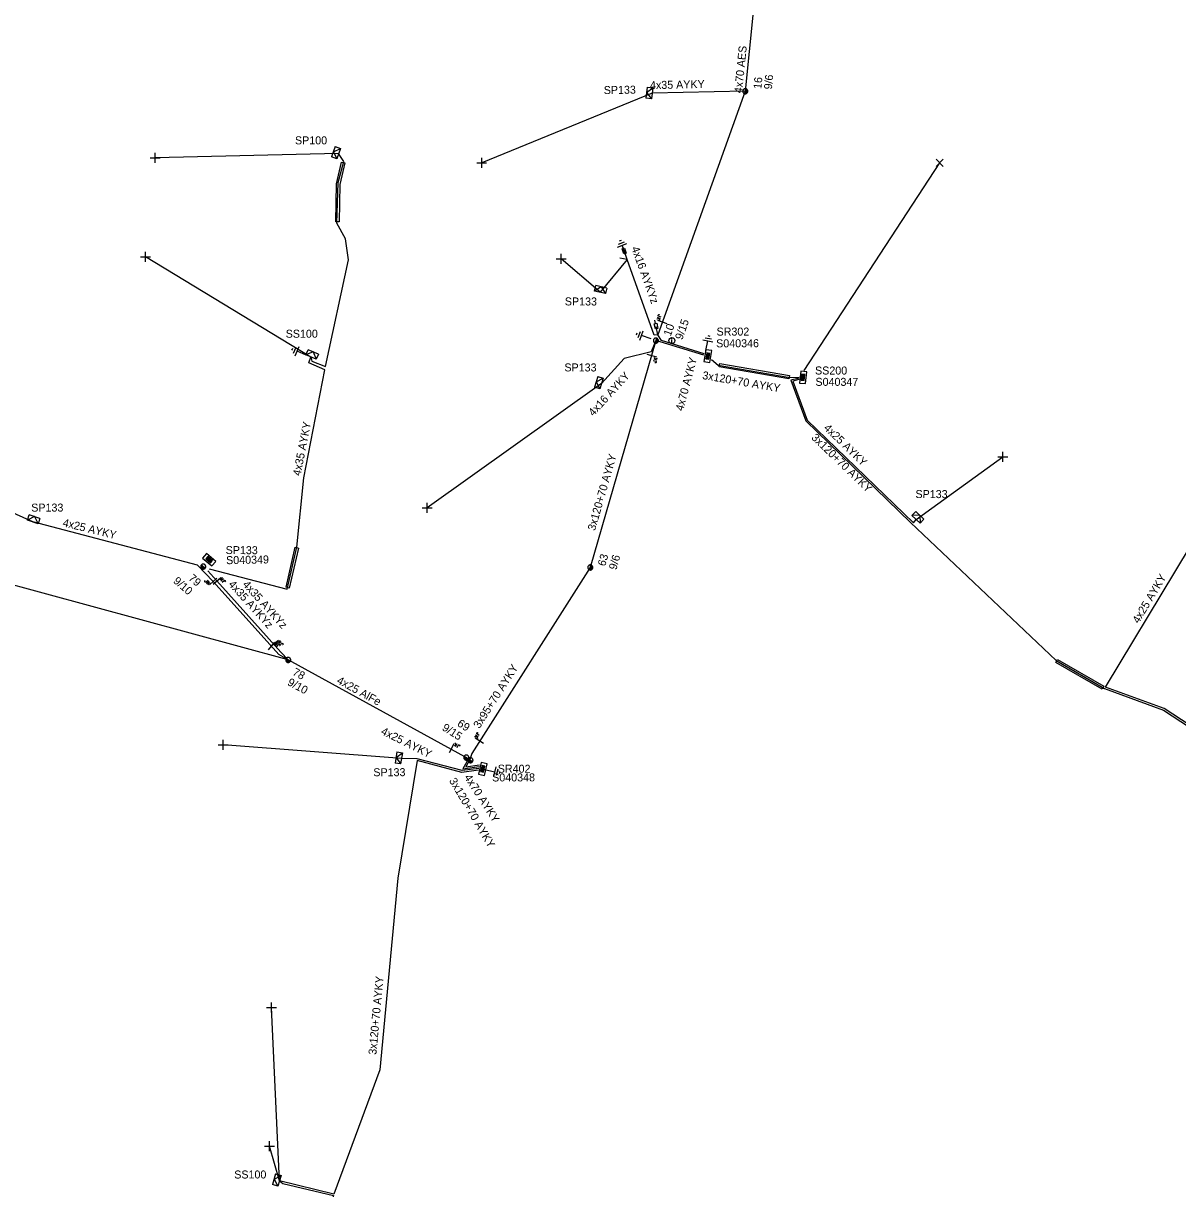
# Model space of a CAD drawing. Extents: x -748492 to -735633, y -1146251 to -1139940.
# Drawn here: x -741045.2 to -740901, y -1144241 to -1144095.3 of the extents above; entities that cross this region are included whole.
import ezdxf

# ---------------------------------------------------------------- set-up
doc = ezdxf.new("R2010")
doc.units = 0
for name, color, linetype in [('Vrstva 1', 7, 'Continuous'), ('Vrstva 10', 7, 'Continuous'), ('Vrstva 12', 7, 'Continuous'), ('Vrstva 13', 7, 'Continuous'), ('Vrstva 14', 7, 'Continuous'), ('Vrstva 15', 7, 'Continuous'), ('Vrstva 16', 7, 'Continuous'), ('Vrstva 18', 7, 'Continuous'), ('Vrstva 2', 7, 'Continuous'), ('Vrstva 20', 7, 'Continuous'), ('Vrstva 28', 7, 'Continuous'), ('Vrstva 29', 7, 'Continuous'), ('Vrstva 30', 7, 'Continuous'), ('Vrstva 31', 7, 'Continuous'), ('Vrstva 33', 7, 'Continuous'), ('Vrstva 34', 7, 'Continuous'), ('Vrstva 36', 7, 'Continuous'), ('Vrstva 5', 7, 'Continuous'), ('Vrstva 50', 7, 'Continuous'), ('Vrstva 51', 7, 'Continuous'), ('Vrstva 52', 7, 'Continuous'), ('Vrstva 53', 7, 'Continuous'), ('Vrstva 54', 7, 'Continuous'), ('Vrstva 55', 7, 'Continuous'), ('Vrstva 59', 7, 'Continuous'), ('Vrstva 6', 7, 'Continuous'), ('Vrstva 8', 7, 'Continuous'), ('Vrstva 9', 7, 'Continuous')]:
    doc.layers.add(name, color=color, linetype=linetype)

# ---------------------------------------------------------------- blocks, each defined once
blk = doc.blocks.new('NN440')
at = {"layer": 'Vrstva 2'}
for points in [[(0.63, 0), (0.63, 0.06), (0.62, 0.13), (0.6, 0.19), (0.58, 0.25), (0.55, 0.31), (0.51, 0.37), (0.47, 0.42), (0.42, 0.46), (0.37, 0.51), (0.32, 0.54), (0.26, 0.57), (0.2, 0.59), (0.13, 0.61), (0.07, 0.62), (0, 0.63), (-0.06, 0.62), (-0.13, 0.61), (-0.19, 0.59), (-0.26, 0.57), (-0.31, 0.54), (-0.37, 0.51), (-0.42, 0.46), (-0.47, 0.42), (-0.51, 0.37), (-0.54, 0.31), (-0.57, 0.25), (-0.6, 0.19), (-0.62, 0.13), (-0.63, 0.06), (-0.63, 0), (-0.63, -0.07), (-0.62, -0.14), (-0.6, -0.2), (-0.57, -0.26), (-0.54, -0.32), (-0.51, -0.37), (-0.47, -0.43), (-0.42, -0.47), (-0.37, -0.51), (-0.31, -0.55), (-0.26, -0.58), (-0.19, -0.6), (-0.13, -0.62), (-0.06, -0.63), (0, -0.63), (0.07, -0.63), (0.13, -0.62), (0.2, -0.6), (0.26, -0.58), (0.32, -0.55), (0.37, -0.51), (0.42, -0.47), (0.47, -0.43), (0.51, -0.37), (0.55, -0.32), (0.58, -0.26), (0.6, -0.2), (0.62, -0.14), (0.63, -0.07), (0.63, 0)], [(-0.63, 0), (0.63, 0)], [(-0.6, -0.18), (0.57, -0.18)], [(-0.51, -0.32), (0.5, -0.32)], [(-0.37, -0.47), (0.35, -0.47)]]:
    blk.add_lwpolyline(points, dxfattribs=at)
blk = doc.blocks.new('NN450')
at = {"layer": 'Vrstva 2'}
for points in [[(0, 0), (0, 0.07), (-0.01, 0.13), (-0.03, 0.19), (-0.05, 0.25), (-0.08, 0.31), (-0.12, 0.37), (-0.16, 0.42), (-0.21, 0.46), (-0.26, 0.51), (-0.31, 0.54), (-0.37, 0.57), (-0.43, 0.59), (-0.5, 0.61), (-0.56, 0.62), (-0.63, 0.62), (-0.69, 0.62), (-0.75, 0.61), (-0.82, 0.59), (-0.88, 0.57), (-0.94, 0.54), (-0.99, 0.51), (-1.04, 0.46), (-1.09, 0.42), (-1.13, 0.37), (-1.17, 0.31), (-1.2, 0.25), (-1.22, 0.19), (-1.24, 0.13), (-1.25, 0.07), (-1.25, 0), (-1.25, -0.07), (-1.24, -0.13), (-1.22, -0.19), (-1.2, -0.25), (-1.17, -0.31), (-1.13, -0.37), (-1.09, -0.42), (-1.04, -0.46), (-0.99, -0.51), (-0.94, -0.54), (-0.88, -0.57), (-0.82, -0.59), (-0.75, -0.61), (-0.69, -0.62), (-0.62, -0.63), (-0.56, -0.62), (-0.5, -0.61), (-0.43, -0.59), (-0.37, -0.57), (-0.31, -0.54), (-0.26, -0.51), (-0.21, -0.46), (-0.16, -0.42), (-0.12, -0.37), (-0.08, -0.31), (-0.05, -0.25), (-0.03, -0.19), (-0.01, -0.13), (0, -0.07), (0, 0)], [(1.25, 0), (1.25, 0.07), (1.24, 0.13), (1.22, 0.19), (1.2, 0.25), (1.17, 0.31), (1.13, 0.37), (1.09, 0.42), (1.04, 0.46), (0.99, 0.51), (0.94, 0.54), (0.88, 0.57), (0.82, 0.59), (0.75, 0.61), (0.69, 0.62), (0.62, 0.62), (0.56, 0.62), (0.5, 0.61), (0.43, 0.59), (0.37, 0.57), (0.31, 0.54), (0.26, 0.51), (0.21, 0.46), (0.16, 0.42), (0.12, 0.37), (0.08, 0.31), (0.05, 0.25), (0.03, 0.19), (0.01, 0.13), (0, 0.07), (0, 0), (0, -0.07), (0.01, -0.13), (0.03, -0.19), (0.05, -0.25), (0.08, -0.31), (0.12, -0.37), (0.16, -0.42), (0.21, -0.46), (0.26, -0.51), (0.31, -0.54), (0.37, -0.57), (0.43, -0.59), (0.5, -0.61), (0.56, -0.62), (0.63, -0.63), (0.69, -0.62), (0.75, -0.61), (0.82, -0.59), (0.88, -0.57), (0.94, -0.54), (0.99, -0.51), (1.04, -0.46), (1.09, -0.42), (1.13, -0.37), (1.17, -0.31), (1.2, -0.25), (1.22, -0.19), (1.24, -0.13), (1.25, -0.07), (1.25, 0)], [(-1.25, 0), (1.25, 0)], [(-1.23, -0.16), (-0.02, -0.16)], [(-1.16, -0.32), (-0.09, -0.32)], [(-1.03, -0.47), (-0.22, -0.47)], [(0.02, -0.16), (1.23, -0.16)], [(0.09, -0.32), (1.16, -0.32)], [(0.22, -0.47), (1.03, -0.47)]]:
    blk.add_lwpolyline(points, dxfattribs=at)
blk = doc.blocks.new('NN840')
at = {"layer": 'Vrstva 15'}
for points in [[(0, 0.62), (0, -0.63)], [(-0.75, -0.71), (-0.75, -0.66)], [(-0.73, -0.76), (-0.75, -0.71)], [(-0.66, -0.8), (-0.73, -0.76)], [(-0.63, -0.8), (-0.66, -0.8)], [(-0.56, -0.76), (-0.63, -0.8)], [(-0.54, -0.71), (-0.56, -0.76)], [(-0.54, -0.38), (-0.54, -0.71)], [(-0.33, -0.38), (-0.33, -0.8)], [(-0.33, -0.64), (-0.13, -0.38)], [(-0.26, -0.56), (-0.09, -0.8)]]:
    blk.add_lwpolyline(points, dxfattribs=at)
blk = doc.blocks.new('NN770')
at = {"layer": 'Vrstva 10'}
for p, q in [((0, 0.19), (0, 0.26)), ((0, -0.28), (0, 0.11))]:
    blk.add_line(p, q, dxfattribs=at)
blk.add_circle((0, -0.01), 0.375, dxfattribs=at)
blk = doc.blocks.new('NN800')
at = {"layer": 'Vrstva 1'}
for points in [[(-0.44, 0.44), (0.44, -0.44)], [(-0.44, -0.44), (0.44, 0.44)]]:
    blk.add_lwpolyline(points, dxfattribs=at)
blk = doc.blocks.new('NN820')
at = {"layer": 'Vrstva 13'}
for points in [[(0, 0), (0, -1.05)], [(-0.16, -0.81), (0.16, -0.81)], [(-0.16, -1.47), (-0.16, -0.81)], [(0, -1.05), (-0.06, -0.93)], [(0, -1.05), (0.06, -0.93)], [(0.16, -0.81), (0.16, -1.47)], [(0.16, -1.47), (-0.16, -1.47)], [(0, -1.47), (0, -1.87)]]:
    blk.add_lwpolyline(points, dxfattribs=at)
blk = doc.blocks.new('NN620')
at = {"layer": 'Vrstva 8'}
for points in [[(0.75, 0), (-0.75, 0)], [(-0.75, 0), (-0.75, -0.75)], [(0.75, -0.75), (0.75, 0)], [(-0.75, -0.75), (0.75, -0.75)], [(0.37, -0.18), (-0.38, -0.18)], [(-0.38, -0.18), (-0.38, -0.56)], [(-0.38, -0.56), (0.37, -0.56)], [(0.32, -0.23), (-0.33, -0.23)], [(-0.33, -0.23), (-0.33, -0.51)], [(-0.33, -0.51), (0.32, -0.51)], [(0.27, -0.27), (-0.28, -0.27)], [(-0.28, -0.27), (-0.28, -0.46)], [(-0.28, -0.46), (0.27, -0.46)], [(0.23, -0.32), (-0.23, -0.32)], [(-0.23, -0.32), (-0.23, -0.42)], [(-0.23, -0.42), (0.23, -0.42)], [(-0.19, -0.37), (0.19, -0.37)], [(0.23, -0.42), (0.23, -0.32)], [(0.27, -0.46), (0.27, -0.27)], [(0.32, -0.51), (0.32, -0.23)], [(0.37, -0.56), (0.37, -0.18)]]:
    blk.add_lwpolyline(points, dxfattribs=at)
blk = doc.blocks.new('NN630')
at = {"layer": 'Vrstva 9'}
for points in [[(0, -0.7), (-0.7, 0)], [(-0.7, -0.7), (-0.7, 0), (0.7, 0), (0.7, -0.7)], [(-0.7, -0.7), (0.7, -0.7)], [(0, -0.7), (0.7, 0)]]:
    blk.add_lwpolyline(points, dxfattribs=at)
blk = doc.blocks.new('NN810')
at = {"layer": 'Vrstva 14'}
for points in [[(0, -0.64), (0, -1.89)], [(0.63, -1.89), (-0.62, -1.89)], [(0.39, -2.2), (-0.4, -2.2)], [(0, -2.52), (-0.12, -2.52)], [(0.14, -2.52), (0, -2.52)]]:
    blk.add_lwpolyline(points, dxfattribs=at)
blk = doc.blocks.new('NN510')
at = {"layer": 'Vrstva 2'}
blk.add_lwpolyline([(0, 0), (0, 0.94)], dxfattribs=at)

msp = doc.modelspace()

# ---------------------------------------------------------------- linework, layer by layer
at = {"layer": 'Vrstva 1'}
for points in [[(-741012.12, -1144174.87), (-741048.89, -1144164.86), (-741086.24, -1144154.83), (-741116.25, -1144144.94)], [(-740989.6, -1144187.24), (-741012.12, -1144174.87)]]:
    msp.add_lwpolyline(points, dxfattribs=at)
at = {"layer": 'Vrstva 20'}
for points in [[(-741005.44, -1144112.67), (-741005.03, -1144112.77), (-741005.67, -1144115.44), (-741005.74, -1144120.13), (-741006.17, -1144120.12), (-741006.1, -1144115.39)], [(-740958.18, -1144137.82), (-740949.47, -1144139.32), (-740949.54, -1144139.74), (-740958.25, -1144138.25)], [(-741012.39, -1144165.8), (-741011.24, -1144160.8), (-741010.84, -1144160.89), (-741012, -1144165.89)], [(-740916.2, -1144175.18), (-740915.98, -1144174.81), (-740910.2, -1144178.17), (-740910.41, -1144178.54)]]:
    msp.add_lwpolyline(points, close=True, dxfattribs=at)
at = {"layer": 'Vrstva 5'}
for points in [[(-741022.01, -1144163.47), (-741012.24, -1144166.05), (-741011.03, -1144160.8), (-741010.17, -1144152.11), (-741007.52, -1144138.63), (-741009.56, -1144137.76), (-741009.27, -1144137.02), (-741009.17, -1144137.55), (-741007.44, -1144138.2), (-741004.59, -1144124.87), (-741004.95, -1144122.26), (-741006.05, -1144120.28), (-741005.89, -1144115.23), (-741005.18, -1144112.58), (-741005.82, -1144111.59)], [(-740960.14, -1144136.6), (-740965.46, -1144134.97), (-740965.92, -1144134.26)], [(-740960.17, -1144136.8), (-740966.17, -1144134.96)], [(-740959.24, -1144137.32), (-740958.39, -1144138.02), (-740949.44, -1144139.56), (-740948.28, -1144139.52)], [(-740948.28, -1144139.66), (-740949.32, -1144139.9), (-740947.42, -1144145.01), (-740934.34, -1144157.68), (-740916.13, -1144174.95), (-740910.1, -1144178.46), (-740902.73, -1144181.13), (-740885.4, -1144192.49), (-740885.11, -1144192.16)], [(-740989.6, -1144187.24), (-740990.28, -1144188.5), (-740988.24, -1144188.21)], [(-740989.18, -1144186.57), (-740989.42, -1144187.33), (-740989.92, -1144188.25), (-740988.2, -1144188)], [(-740988.35, -1144188.63), (-740990.41, -1144188.92), (-740996.02, -1144187.44), (-740998.41, -1144202.15), (-741000.67, -1144226.1), (-741006.41, -1144241.62), (-741013.22, -1144239.98), (-741012.79, -1144240.29), (-741006.47, -1144241.81), (-741012.77, -1144265.77), (-741010.65, -1144272.99), (-741011.74, -1144282.71), (-741012.93, -1144282.43)]]:
    msp.add_lwpolyline(points, dxfattribs=at)
at = {"layer": 'Vrstva 50'}
msp.add_lwpolyline([(-740946.1, -1144042.17), (-740951.92, -1144073.19), (-740955, -1144103.8), (-740965.92, -1144134.26)], dxfattribs=at)
at = {"layer": 'Vrstva 52'}
for points in [[(-740955, -1144103.8), (-740966.64, -1144104.06)], [(-740885.27, -1144192.03), (-740885.46, -1144192.21), (-740902.64, -1144180.95), (-740909.99, -1144178.29), (-740883.61, -1144134.55), (-740882.09, -1144133.72)], [(-740966.17, -1144134.96), (-740974.37, -1144163.32), (-740989.18, -1144186.57)], [(-740966.17, -1144134.96), (-740966.77, -1144136.35), (-740970.14, -1144137.21), (-740972.97, -1144140.32)], [(-740948.3, -1144139.82), (-740949.06, -1144140.02), (-740947.25, -1144144.9), (-740933.99, -1144157.73), (-740933.66, -1144157.31)], [(-741023.46, -1144163.01), (-741044.03, -1144157.63)], [(-741012.12, -1144174.87), (-741013.28, -1144174.21), (-741021.49, -1144165.08), (-741023.46, -1144163.01)], [(-741022.17, -1144163.73), (-741021.02, -1144164.99), (-741013.02, -1144173.89), (-741012.12, -1144174.87)], [(-740988.29, -1144188.42), (-740990.39, -1144188.71), (-740995.99, -1144187.24), (-740997.95, -1144187.18)]]:
    msp.add_lwpolyline(points, dxfattribs=at)
at = {"layer": 'Vrstva 54'}
msp.add_lwpolyline([(-740965.92, -1144134.26), (-740966.4, -1144134.3), (-740969.74, -1144124.84), (-740973.15, -1144128.93)], dxfattribs=at)
at = {"layer": 'Vrstva 59'}
for points in [[(-740966.64, -1144104.06), (-740987.94, -1144112.75)], [(-741005.82, -1144111.6), (-741028.75, -1144112.13)], [(-740947.63, -1144138.7), (-740930.69, -1144112.75)], [(-741009.27, -1144137.02), (-741029.94, -1144124.5)], [(-740973.15, -1144128.93), (-740978, -1144124.75)], [(-740972.97, -1144140.32), (-740994.75, -1144155.88)], [(-741044.03, -1144157.63), (-741076.63, -1144143)], [(-740933.66, -1144157.31), (-740922.81, -1144149.5)], [(-740997.95, -1144187.18), (-741020.25, -1144185.5)], [(-741013.22, -1144239.98), (-741014.19, -1144218.3)], [(-741013.22, -1144239.98), (-741014.45, -1144235.62)]]:
    msp.add_lwpolyline(points, dxfattribs=at)

# ---------------------------------------------------------------- block references
at = {"layer": 'Vrstva 13'}
for name, p, xscale, yscale, rotation in [('NN440', (-740955, -1144103.8), 0.49999999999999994, 0.5000000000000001, 84.2955472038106), ('NN440', (-740966.17, -1144134.96), 0.5, 0.5, 70.52858330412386), ('NN440', (-741022.73, -1144163.2), 0.5, 0.5, -40.86051949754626), ('NN440', (-740974.37, -1144163.32), 0.5, 0.5, 73.87332228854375), ('NN440', (-741012.12, -1144174.87), 0.5, 0.5, -28.28923612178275), ('NN450', (-740989.6, -1144187.24), 0.5, 0.5000000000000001, -32.633441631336)]:
    msp.add_blockref(name, p, dxfattribs=dict(at, xscale=xscale, yscale=yscale, rotation=rotation))
at = {"layer": 'Vrstva 13', "rotation": 78.00008328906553}
msp.add_blockref('NN510', (-740969.74, -1144124.84), dxfattribs=at)
at = {"layer": 'Vrstva 15'}
for p, rotation in [((-740969.74, -1144124.84), -160.2392472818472), ((-740966.17, -1144134.96), -109.4714166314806), ((-740960.05, -1144136.84), 168.6360666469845), ((-741009.27, -1144137.02), -112.95754439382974), ((-740988.16, -1144188.4), 76.60303609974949)]:
    msp.add_blockref('NN810', p, dxfattribs=dict(at, rotation=rotation))
at = {"layer": 'Vrstva 16'}
for p, rotation in [((-740969.74, -1144124.84), -160.2392472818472), ((-740965.92, -1144134.26), -168.5325388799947)]:
    msp.add_blockref('NN820', p, dxfattribs=dict(at, rotation=rotation))
at = {"layer": 'Vrstva 18'}
for p, rotation in [((-740965.35, -1144132.67), -110.33704722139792), ((-740966.71, -1144136.84), 73.8170500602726), ((-741021.49, -1144165.08), -48.44668063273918), ((-741021.02, -1144164.99), 131.07454443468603), ((-741014.19, -1144173.13), 138.61206670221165), ((-741013.82, -1144172.79), 126.60870547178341), ((-740988.23, -1144184.99), -123.71592498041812), ((-740991.67, -1144185.88), 151.71076391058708)]:
    msp.add_blockref('NN840', p, dxfattribs=dict(at, rotation=rotation))
at = {"layer": 'Vrstva 28'}
for p, rotation in [((-740960.05, -1144136.84), 80.7175583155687), ((-740948.14, -1144139.52), 84.01704442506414), ((-741022.24, -1144162.63), 139.13899995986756), ((-740988.16, -1144188.4), 76.68470000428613)]:
    msp.add_blockref('NN620', p, dxfattribs=dict(at, rotation=rotation))
at = {"layer": 'Vrstva 31'}
for p, rotation in [((-740966.64, -1144104.06), -96.95990000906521), ((-741005.82, -1144111.6), -109.9655860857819), ((-740973.15, -1144128.93), 167.5300471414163), ((-741009.27, -1144137.02), 157.04245551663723), ((-740972.97, -1144140.32), -107.82400830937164), ((-740933.66, -1144157.31), 136.7943583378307), ((-741044.03, -1144157.63), 161.63737237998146), ((-740997.95, -1144187.18), -99.3960388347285), ((-741013.22, -1144239.98), -106.94598609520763)]:
    msp.add_blockref('NN630', p, dxfattribs=dict(at, rotation=rotation))
at = {"layer": 'Vrstva 34'}
for p, rotation in [((-741028.75, -1144112.13), 45), ((-740987.94, -1144112.75), 44.99999995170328), ((-741029.94, -1144124.5), 44.99999995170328), ((-740978, -1144124.75), 45), ((-740922.81, -1144149.5), 45), ((-740994.75, -1144155.88), 45), ((-741020.25, -1144185.5), 45), ((-741014.19, -1144218.3), 45), ((-741014.45, -1144235.62), 45.000000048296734)]:
    msp.add_blockref('NN800', p, dxfattribs=dict(at, rotation=rotation))
msp.add_blockref('NN800', (-740930.69, -1144112.75), dxfattribs=at)
at = {"layer": 'Vrstva 36'}
msp.add_blockref('NN770', (-740964.17, -1144134.96), dxfattribs=at)

# ---------------------------------------------------------------- texts
at = {"layer": 'Vrstva 12'}
for s, rotation, p in [('9/6', 84.296, (-740951.68, -1144103.62)), ('9/15', 70.529, (-740962.88, -1144134.95)), ('9/6', 73.873, (-740971.12, -1144163.69)), ('9/10', 319.139, (-741026.57, -1144165.13)), ('9/10', 331.711, (-741012.3, -1144177.96)), ('9/15', 327.367, (-740992.98, -1144183.57))]:
    msp.add_text(s, height=1, rotation=rotation, dxfattribs=at).set_placement(p)
at = {"layer": 'Vrstva 14'}
for s, rotation, p in [('16', 84.296, (-740953, -1144103.56)), ('10', 70.529, (-740964.32, -1144134.49)), ('63', 73.873, (-740972.51, -1144163.23)), ('79', 319.139, (-741024.67, -1144164.79)), ('78', 331.711, (-741011.67, -1144176.69)), ('69', 327.367, (-740991.08, -1144183.05))]:
    msp.add_text(s, height=1, rotation=rotation, dxfattribs=at).set_placement(p)
at = {"layer": 'Vrstva 2'}
msp.add_text('4x25 AlFe', height=1, rotation=331.22, dxfattribs=at).set_placement((-741006.14, -1144177.73))
at = {"layer": 'Vrstva 29'}
for s, rotation, p in [('S040346', 0.183, (-740958.64, -1144135.81)), ('S040347', 359.952, (-740946.23, -1144140.62)), ('S040349', 1.106, (-741019.87, -1144162.91)), ('S040348', 0.14, (-740986.63, -1144190.06))]:
    msp.add_text(s, height=1, rotation=rotation, dxfattribs=at).set_placement(p)
at = {"layer": 'Vrstva 30'}
for s, rotation, p in [('SR302', 359.99, (-740958.59, -1144134.34)), ('SS200', 359.839, (-740946.28, -1144139.2)), ('SP133', 359.622, (-741019.94, -1144161.64)), ('SR402', 359.832, (-740985.93, -1144188.96))]:
    msp.add_text(s, height=1, rotation=rotation, dxfattribs=at).set_placement(p)
at = {"layer": 'Vrstva 33'}
for s, rotation, p in [('SP133', 0.776, (-740972.68, -1144104.16)), ('SP100', 359.93, (-741011.27, -1144110.44)), ('SP133', 359.88, (-740977.55, -1144130.57)), ('SS100', 0.08, (-741012.43, -1144134.61)), ('SP133', 359.983, (-740977.6, -1144138.82)), ('SP133', 359.86, (-740933.73, -1144154.64)), ('SP133', 0.126, (-741044.23, -1144156.34)), ('SP133', 0.148, (-741001.48, -1144189.41)), ('SS100', 0.125, (-741018.86, -1144239.68))]:
    msp.add_text(s, height=1, rotation=rotation, dxfattribs=at).set_placement(p)
at = {"layer": 'Vrstva 51'}
msp.add_text('4x70 AES', height=1, rotation=84.254, dxfattribs=at).set_placement((-740955.4, -1144104.09))
at = {"layer": 'Vrstva 53'}
for s, rotation, p in [('4x35 AYKYz', 312.008, (-741019.66, -1144165.47)), ('4x35 AYKYz', 312.005, (-741017.89, -1144165.5)), ('3x95+70 AYKY', 57.514, (-740988.22, -1144183.52))]:
    msp.add_text(s, height=1, rotation=rotation, dxfattribs=at).set_placement(p)
at = {"layer": 'Vrstva 54'}
for s, rotation, p in [('4x35 AYKY', 1.28, (-740966.9, -1144103.55)), ('4x16 AYKY', 47.521, (-740973.98, -1144144.49)), ('4x25 AYKY', 315.919, (-740945.27, -1144145.98)), ('4x25 AYKY', 346.291, (-741040.37, -1144158.16)), ('4x25 AYKY', 58.983, (-740905.85, -1144170.4)), ('4x25 AYKY', 333.533, (-741000.62, -1144184.11))]:
    msp.add_text(s, height=1, rotation=rotation, dxfattribs=at).set_placement(p)
at = {"layer": 'Vrstva 55'}
msp.add_text('4x16 AYKYz', height=1, rotation=289.751, dxfattribs=at).set_placement((-740969.25, -1144123.4))
at = {"layer": 'Vrstva 6'}
for s, rotation, p in [('4x70 AYKY', 75.087, (-740962.78, -1144143.83)), ('3x120+70 AYKY', 350.307, (-740960.42, -1144139.76)), ('4x35 AYKY', 78.881, (-741010.58, -1144151.93)), ('3x120+70 AYKY', 315.919, (-740946.82, -1144147.18)), ('3x120+70 AYKY', 74.126, (-740973.77, -1144158.79)), ('3x120+70 AYKY', 300.417, (-740992.05, -1144189.96)), ('4x70 AYKY', 302.72, (-740990.17, -1144189.54)), ('3x120+70 AYKY', 84.615, (-741001.11, -1144224.25))]:
    msp.add_text(s, height=1, rotation=rotation, dxfattribs=at).set_placement(p)

doc.saveas('drawing.dxf')
